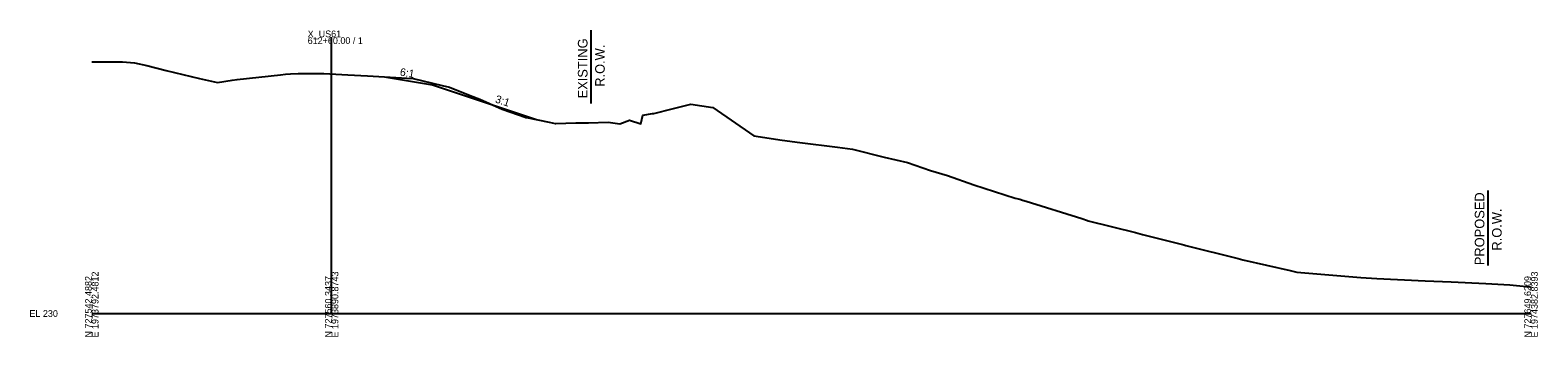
# Model space of a CAD drawing. Extents: x -26 to 1604, y -13 to 9623.
# Drawn here: x -26 to 603, y 1490 to 1618 of the extents above; entities that cross this region are included whole.
import ezdxf

# ---------------------------------------------------------------- set-up
doc = ezdxf.new("R2010")
doc.units = 0
for name, color, linetype in [('Default', 7, 'Continuous'), ('Draft_XS_Grid', 7, 'Continuous'), ('DTM_X_GROUND', 7, 'Continuous'), ('XS_CELL', 7, 'Continuous'), ('XS_P_GROUND', 7, 'Continuous'), ('XS_P_ROW', 7, 'Continuous'), ('XS_P_TX_FS_BS', 7, 'Continuous'), ('XS_X_ROW', 7, 'Continuous')]:
    doc.layers.add(name, color=color, linetype=linetype)

msp = doc.modelspace()

# ---------------------------------------------------------------- linework, layer by layer
at = {"layer": 'DTM_X_GROUND'}
msp.add_lwpolyline([(0, 1604.74), (12.8, 1604.76), (12.83, 1604.76), (17.84, 1604.31), (23.01, 1603.27), (31.02, 1601.13), (44.93, 1597.86), (52.36, 1596.22), (58.53, 1597.15), (60.56, 1597.45), (78.62, 1599.39), (80.7, 1599.63), (82.78, 1599.74), (86.02, 1599.91), (93.81, 1599.94), (94.4, 1599.95), (96.74, 1599.95), (106.68, 1599.4), (114.94, 1598.89), (129.15, 1598.13), (131.39, 1597.92), (133.98, 1597.78), (146.02, 1594.93), (149.11, 1594.25), (156.39, 1591.36), (160.69, 1589.67), (161.73, 1589.29), (171.13, 1585.11), (180.71, 1581.77), (180.92, 1581.58), (181.29, 1581.53), (190.74, 1579.65), (193.23, 1579.15), (193.3, 1579.14), (193.39, 1579.14), (201.8, 1579.42), (205.4, 1579.37), (207.13, 1579.43), (215.23, 1579.69), (220.18, 1578.99), (224.14, 1580.5), (228.84, 1578.96), (229.71, 1582.63), (233.73, 1583.25), (234.3, 1583.28), (242, 1585.21), (249.74, 1587.15), (258.96, 1585.69), (275.95, 1573.97), (287.84, 1572.22), (295.13, 1571.2), (310.91, 1569.26), (317.17, 1568.41), (330.34, 1565.07), (340.02, 1562.89), (349.61, 1559.5), (356.67, 1557.43), (367.71, 1553.56), (384.94, 1548.08), (386.95, 1547.56), (388.01, 1547.2), (389.52, 1546.72), (412.68, 1539.49), (415.12, 1538.73), (415.4, 1538.65), (435.1, 1533.67), (438.06, 1532.9), (455.22, 1528.6), (456.12, 1528.37), (477.84, 1522.84), (479.83, 1522.35), (499.57, 1517.84), (502.35, 1517.27), (529, 1515.06), (535.67, 1514.6), (555.93, 1513.64), (566.75, 1513.15), (581.17, 1512.54), (591.16, 1511.97), (599.56, 1511.07), (600, 1511.03)], dxfattribs=at)
at = {"layer": 'XS_CELL'}
for p, q in [((100, 1500), (100, 1615)), ((0, 1500), (100, 1500)), ((100, 1500), (600, 1500))]:
    msp.add_line(p, q, dxfattribs=at)
at = {"layer": 'XS_P_GROUND'}
for points in [[(122, 1598.51), (142, 1595.18)], [(142, 1595.18), (185.36, 1580.73)]]:
    msp.add_lwpolyline(points, dxfattribs=at)
at = {"layer": 'XS_P_ROW'}
msp.add_line((582, 1551.27), (582, 1520), dxfattribs=at)
at = {"layer": 'XS_X_ROW'}
msp.add_line((208, 1617.94), (208, 1587.39), dxfattribs=at)

# ---------------------------------------------------------------- texts
at = {"layer": 'Default'}
for p in [(121.96, 1598.45), (141.96, 1595.12), (141.96, 1595.12), (185.32, 1580.67)]:
    msp.add_text('X', height=0.12, dxfattribs=at).set_placement(p)
at = {"layer": 'Draft_XS_Grid'}
msp.add_text('-', height=0.0001, dxfattribs=at).set_placement((0, 1500))
at = {"layer": 'XS_CELL'}
for s, p in [('X_US61', (90, 1615)), ('612+60.00 / 1', (90, 1612.2)), ('EL 230', (-26, 1498.6))]:
    msp.add_text(s, height=2.8, dxfattribs=at).set_placement(p)
for s, p in [('N 727542.4882', (0, 1490)), ('E 1973792.4812', (2.8, 1490)), ('N 727560.3437', (100, 1490)), ('E 1973890.8743', (102.8, 1490)), ('N 727649.6209', (600, 1490)), ('E 1974382.8393', (602.8, 1490))]:
    msp.add_text(s, height=2.8, rotation=90, dxfattribs=at).set_placement(p)
at = {"layer": 'XS_P_ROW'}
for s, p in [('PROPOSED', (580.55, 1520.13)), ('R.O.W.', (587.75, 1526.2))]:
    msp.add_text(s, height=4, rotation=90, dxfattribs=at).set_placement(p)
at = {"layer": 'XS_P_TX_FS_BS'}
for s, rotation, p in [('6:1', 350.53766, (128.28, 1599.06)), ('3:1', 341.56507, (167.9, 1587.96))]:
    msp.add_text(s, height=3.24, rotation=rotation, dxfattribs=at).set_placement(p)
at = {"layer": 'XS_X_ROW'}
for s, p in [('EXISTING', (206.65, 1589.55)), ('R.O.W.', (213.85, 1594.4))]:
    msp.add_text(s, height=4, rotation=90, dxfattribs=at).set_placement(p)

doc.saveas('drawing.dxf')
